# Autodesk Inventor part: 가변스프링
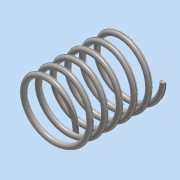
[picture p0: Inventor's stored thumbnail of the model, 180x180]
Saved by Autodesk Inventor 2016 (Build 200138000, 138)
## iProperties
Created: 2018-11
Part Number: 가변스프링
Material: 스테인레스 스틸
Document SubType Name: Sheet Metal
Designer: user
Density: 8 g/cm^3
Sheet Metal Rule: 기본값_mm
Appearance: 반연마
Mass: 84.1985 g
Surface Area: 106.475 cm^2
Volume: 10.5248 cm^3
Author: user
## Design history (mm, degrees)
sketch "스케치1"
  geometry: L1 (0, 0)-(22.5, 0); L2 (22.5, 0)-(22.5, 67.25); L3 (22.5, 67.25)-(0, 67.25); L4 (0, 67.25)-(0, 0); C1 r 2 at (22.5, 0)
  constraints: 8 end point, 2 parallel, 1 centre point, 1 coincident, 1 horizontal, 1 perpendicular
  dimensions: "d0" = 45 diameter of L2 L4; "d1" = 67.25 distance of L3.end L1.start (derived); "d2" = 4 diameter of C1
feature "코일1" sketch "스케치1" pitch "d3" = 10; turns "d5" = 6; dims "d4" = 67.25 (= d1), "d6" = 0, angle "d7" = 90 deg, angle "d8" = 90 deg, "d9" = 0, "d10" = 0
sketch "스케치2"
  geometry: L1 (-32.5, 0)-(32.5, 0); L2 (32.5, 0)-(32.5, 80); L3 (32.5, 80)-(-32.5, 80); L4 (-32.5, 80)-(-32.5, 0); 2 further points
  constraints: 8 end point, 2 coincident, 2 parallel, 1 horizontal, 1 midpoint, 1 perpendicular
  dimensions: "d11" = 80 distance of L3.end L1.start; "d12" = 65 distance between parallel lines of L2 L4
extrude "돌출1" sketch "스케치2" stored distance "d13" = 300; taper "d14" = 0 deg
sketch "스케치3"
  geometry: L1 (-37.872, 0)-(43.547, 0); L2 (24.5, 67.25)-(-35.5, 67.25); L3 (-35.5, 67.25)-(-35.5, 0); L4 (-35.5, 0)-(24.5, 0); L5 (24.5, 0)-(24.5, 67.25); 2 further points
  constraints: 10 end point, 2 horizontal, 2 parallel, 1 horizontal alignment, 1 midpoint, 1 perpendicular
  dimensions: "d16" = 60 distance of L2.start L2.end
extrude "돌출2" sketch "스케치3" stored distance "d17" = 300; taper "d18" = 0 deg
node "솔리드1"
other parameters: "BendRadius" = 0.5 (derived), "BendReliefWidth" = 0.5 (derived), "BendReliefDepth" = 0.25 (derived), "CornerReliefSize" = 2 (derived), "SeamGap" = 0.01, "MinimumRemnant" = 1 (derived), "TransitionRadius" = 0.5 (= BendRadius)
